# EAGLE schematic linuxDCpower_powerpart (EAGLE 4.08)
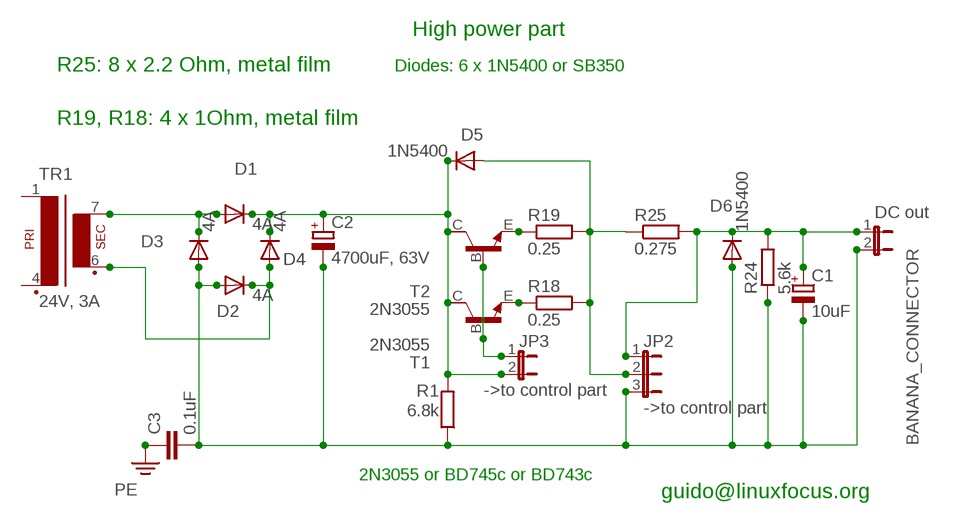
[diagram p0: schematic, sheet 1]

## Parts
BANANA_CONNECTOR  DC out  JP1E  [JP1]
C1  10uF  CPOL-EUE3.5-8  [E3,5-8]
C2  4700uF, 63V  CPOL-EUE10-30  [EB30D]
C3  0.1uF  C-EU025-060X050  [C025-060X050]
D1  4A  BY550  [DO27-15]
D2  4A  BY550  [DO27-15]
D3  4A  BY550  [DO27-15]
D4  4A  BY550  [DO27-15]
D5  1N5400  1N4004  [DO41-10]
D6  1N5400  1N4004  [DO41-10]
JP2  ->to control part  JP2E  [JP2]
JP3  ->to control part  JP1E  [JP1]
R1  6.8k  R-EU_0204/7  [0204/7]
R18  0.25  R-EU_0204/7  [0204/7]
R19  0.25  R-EU_0204/7  [0204/7]
R24  5.6k  R-EU_0204/7  [0204/7]
R25  0.275  R-EU_0204/7  [0204/7]
T1  2N3055  [TO3]
T2  2N3055  [TO3]
TR1  24V, 3A  EE20-1  [EE20-1]

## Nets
N$1: D1.A D3.C TR1.7
N$2: C2.+ D1.C D4.C D5.C JP3.2 R1.2 T1.C T2.C
N$3: JP3.1 T1.B T2.B
N$7: D5.A JP2.2 R18.2 R19.2 R25.1
N$9: D2.C D4.A TR1.6
N$12: BANANA_CONNECTOR.1 C1.+ D6.C JP2.1 R24.2 R25.2
N$14: BANANA_CONNECTOR.2 C1.- C2.- C3.2 D2.A D3.A D6.A JP2.3 R1.1 R24.1
N$17: R19.1 T2.E
N$18: R18.1 T1.E
PE: C3.1
Unconnected: T1.C/(C) T2.C/(C) TR1.1 TR1.4

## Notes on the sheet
- High power part
- R25: 8 x 2.2 Ohm, metal film | Diodes: 6 x 1N5400 or SB350
- R19, R18: 4 x 1Ohm, metal film
- 2N3055 or BD745c or BD743c
- guido@linuxfocus.org

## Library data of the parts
BANANA_CONNECTOR JP3 = jumper:JP1E: JUMPER
C1 C2 = rcl:CPOL-EU: POLARIZED CAPACITOR, European symbol
C3 = rcl:C-EU: CAPACITOR, European symbol
D1-D4 = diode:BY550: DIODE
D5 D6 = diode:1N4004: DIODE
JP2 = jumper:JP2E: JUMPER
R1 R18 R19 R24 R25 = rcl:R-EU_: RESISTOR, European symbol
T1 T2 = transistor-npn:2N3055: NPN TRANSISTOR
TR1 = trafo:EE20-1: TRANSFORMER 1 primary winding, 1 secondary winding ERA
